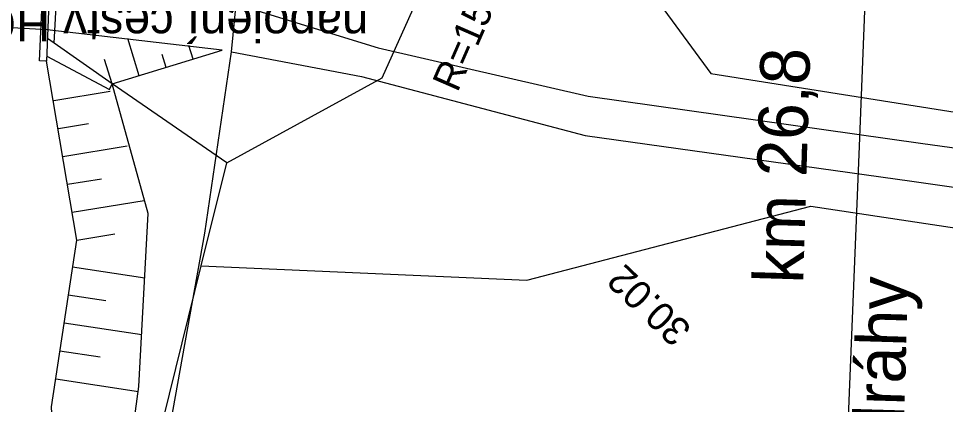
# Model space of a CAD drawing. Extents: x -583470 to -583050, y -1165714 to -1165417.
# Drawn here: x -583387.2 to -583321.6, y -1165666.4 to -1165639.1 of the extents above; entities that cross this region are included whole.
import ezdxf

# ---------------------------------------------------------------- set-up
doc = ezdxf.new("R2010")
doc.units = 0
for name, color, linetype in [('22', 7, 'Continuous'), ('42', 7, 'Continuous'), ('60', 7, 'Continuous'), ('62', 7, 'Continuous'), ('Hranice parcel', 7, 'Continuous'), ('Rám', 7, 'Continuous'), ('Sítě', 7, 'Continuous'), ('Šrafy', 7, 'Continuous')]:
    doc.layers.add(name, color=color, linetype=linetype)

msp = doc.modelspace()

# ---------------------------------------------------------------- linework, layer by layer
at = {"layer": '22'}
for points in [[(-583385.3, -1165633.85), (-583384.86, -1165633.85), (-583385.19, -1165642.1), (-583385.68, -1165642.08), (-583385.3, -1165633.85)], [(-583385.14, -1165639.88), (-583389.74, -1165639.62)], [(-583385.17, -1165641.75), (-583380.74, -1165644.1), (-583380.56, -1165643.71), (-583385.12, -1165640.49)]]:
    msp.add_lwpolyline(points, dxfattribs=at)
at = {"layer": '42'}
for points in [[(-583372.77, -1165641.33), (-583385.14, -1165639.88)], [(-583380.56, -1165643.71), (-583372.77, -1165641.33)], [(-583383.586, -1165694.294), (-583383.47, -1165691.82), (-583384.84, -1165666.54), (-583383.06, -1165654.75), (-583385.19, -1165642.1)], [(-583381.667, -1165694.427), (-583381.45, -1165685.69), (-583378.66, -1165665.11), (-583378, -1165652.86), (-583380.56, -1165643.71)]]:
    msp.add_lwpolyline(points, dxfattribs=at)
at = {"layer": '60'}
for points in [[(-583378.65, -1165643.13), (-583379.45, -1165640.51)], [(-583374.82, -1165641.96), (-583375.12, -1165640.99)], [(-583376.73, -1165642.54), (-583377.01, -1165641.64)], [(-583372.91, -1165641.37), (-583372.93, -1165641.3)], [(-583380.56, -1165643.71), (-583381.09, -1165641.99)], [(-583384.67, -1165644.88), (-583380.7, -1165644.23)], [(-583384.35, -1165646.85), (-583382.22, -1165646.51)], [(-583384.03, -1165648.83), (-583379.49, -1165648.09)], [(-583383.7, -1165650.8), (-583381.3, -1165650.41)], [(-583383.38, -1165652.78), (-583378.29, -1165651.94)], [(-583383.06, -1165654.75), (-583380.37, -1165654.31)], [(-583383.35, -1165656.65), (-583378.25, -1165657.42)], [(-583383.65, -1165658.63), (-583381, -1165659.03)], [(-583383.94, -1165660.61), (-583378.46, -1165661.43)], [(-583384.24, -1165662.58), (-583381.41, -1165663.01)], [(-583384.54, -1165664.56), (-583378.68, -1165665.45)]]:
    msp.add_lwpolyline(points, dxfattribs=at)
at = {"layer": '62'}
for points in [[(-583379.741, -1165694.56), (-583379.57, -1165690.87), (-583377.81, -1165675.52), (-583374, -1165654.25), (-583372.12, -1165641.43), (-583371.79, -1165638.08), (-583372.3, -1165610.54), (-583370.49, -1165593.91), (-583364.41, -1165578.01), (-583353.13, -1165562.49), (-583348.06, -1165556.64), (-583342.86, -1165548.6), (-583339.71, -1165538.95), (-583338.99, -1165532.81), (-583338.38, -1165526.75), (-583340.63, -1165516.91), (-583347.05, -1165504.24), (-583349.624, -1165498.549)], [(-583371.79, -1165638.08), (-583361.74, -1165641.15), (-583346.91, -1165644.58), (-583323.24, -1165647.92), (-583297.05, -1165651.52), (-583281.69, -1165654.07), (-583264.82, -1165656.96), (-583238.56, -1165662.27)], [(-583372.12, -1165641.43), (-583362.92, -1165643.19), (-583347.12, -1165647.36), (-583324.02, -1165650.58), (-583297.11, -1165654.42), (-583282.31, -1165656.2), (-583265.24, -1165659.25), (-583242.08, -1165665.94)]]:
    msp.add_lwpolyline(points, dxfattribs=at)
at = {"layer": 'Rám'}
msp.add_line((-583374.25, -1165656.58), (-583372.44, -1165649.28), dxfattribs=at)
for points in [[(-583372.44, -1165649.28), (-583380.56, -1165643.71), (-583384.65, -1165640.82), (-583384.34, -1165635.13), (-583380.11, -1165632.63), (-583380.02, -1165632.08), (-583374.92, -1165587.93), (-583361.04, -1165570.69)], [(-583372.44, -1165649.28), (-583361.47, -1165643.29), (-583352.56, -1165623.43)], [(-583352.56, -1165623.43), (-583338.23, -1165642.98), (-583317.68, -1165646.22), (-583282.91, -1165650.36), (-583267.19, -1165652.43), (-583242.28, -1165656.94), (-583228.69, -1165666.2)], [(-583374.25, -1165656.58), (-583351.23, -1165657.59), (-583331.17, -1165652.35), (-583245.16, -1165665.31), (-583236.84, -1165691.62), (-583236.794, -1165692.442)], [(-583381.45, -1165700.418), (-583381.45, -1165685.69), (-583374.25, -1165656.58)]]:
    msp.add_lwpolyline(points, dxfattribs=at)
at = {"layer": 'Šrafy'}
msp.add_lwpolyline([(-583330.415, -1165714.314), (-583327.729, -1165648.098), (-583326.961, -1165628.953), (-583325.947, -1165605.218), (-583324.898, -1165585.029), (-583322.506, -1165553.54), (-583320.453, -1165533.822), (-583317.86, -1165513.431), (-583313.388, -1165484.957)], dxfattribs=at)

# ---------------------------------------------------------------- texts
at = {"layer": 'Hranice parcel'}
for s, rotation, p in [('R=15m alfa=40.11%%d', 66.38999, (-583356.145, -1165644.366)), ('30.02', 136.33647, (-583339.495, -1165660.965))]:
    msp.add_text(s, height=2, rotation=rotation, dxfattribs=at).set_placement(p)
at = {"layer": 'Sítě'}
for s, height, rotation, p in [('napojení cesty HC5a na zpevněnou část M5', 2.50002, 180, (-583362.443, -1165638.207)), ('km 26,8', 3.5, 88.30576, (-583331.704, -1165657.848)), ('ochranné pásmo dráhy', 3.5, 88.30576, (-583325.698, -1165705.229))]:
    msp.add_text(s, height=height, rotation=rotation, dxfattribs=at).set_placement(p)

doc.saveas('drawing.dxf')
